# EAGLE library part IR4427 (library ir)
DUAL LOW SIDE DRIVER Source: ID4426.pdf
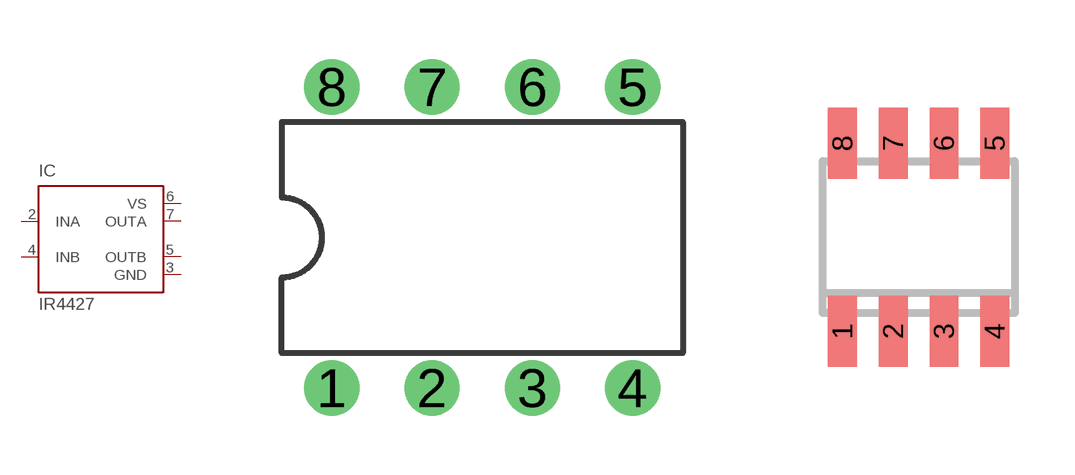
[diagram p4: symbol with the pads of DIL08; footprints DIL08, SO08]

Designator prefix IC

## IR4427 (MF: INTERNATIONAL RECTIFIER(IR); MPN: IR4427; OC_FARNELL: 1023267; OC_NEWARK: 27C6914)  [DIL08]
2  INA  in
3  GND  pwr
4  INB  in
5  OUTB  out
6  VS  pwr
7  OUTA  out

## IR4427S (MF: INTERNATIONAL RECTIFIER(IR); MPN: IR4427STRPBF; OC_FARNELL: 8639094; OC_NEWARK: 63J7933)  [SO08]
Pads as for DIL08

## Footprint DIL08 (pad centres in mm)
Dual In Line Package
drill 0.8 pad 1.4 round: 1 -3.81,-3.81; 2 -1.27,-3.81; 3 1.27,-3.81; 4 3.81,-3.81; 5 3.81,3.81; 6 1.27,3.81; 7 -1.27,3.81; 8 -3.81,3.81

## Footprint SO08 (pad centres in mm)
8 Lead SOIC Data Sheet No. PD60212 Rev A Source: www.irf.com .. ir2520.pdf
smd 0.72 x 1.78: 1 -1.905,-2.35; 2 -0.635,-2.35; 3 0.635,-2.35; 4 1.905,-2.35; 5 1.905,2.35; 6 0.635,2.35; 7 -0.635,2.35; 8 -1.905,2.35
